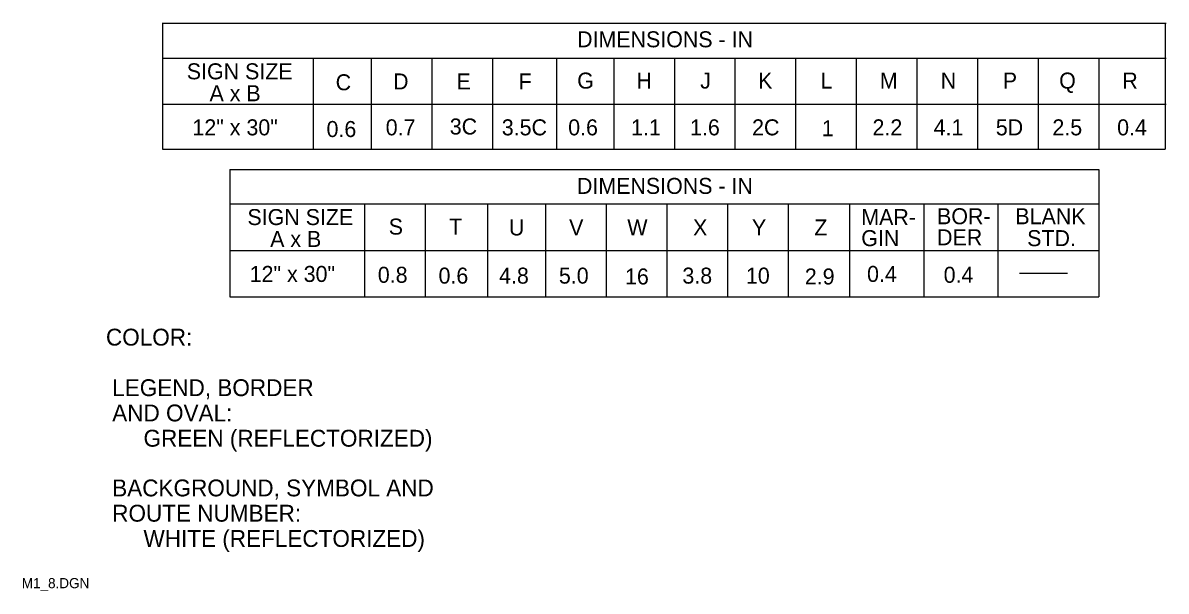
# Model space of a CAD drawing. Extents: x 0.013 to 0.192, y 0.004 to 0.259.
# Drawn here: x 0.0127 to 0.1824, y 0.0039 to 0.0882 of the extents above; entities that cross this region are included whole.
import ezdxf

# ---------------------------------------------------------------- set-up
doc = ezdxf.new("R2010")
doc.units = 0
doc.layers.add('1', color=7, linetype='Continuous')
doc.layers.add('3', color=7, linetype='Continuous')

msp = doc.modelspace()

# ---------------------------------------------------------------- linework, layer by layer
at = {"layer": '1'}
msp.add_line((0.160625, 0.051125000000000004), (0.16775, 0.051125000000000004), dxfattribs=at)
at = {"layer": '3'}
for p, q in [((0.033375, 0.08825), (0.033375, 0.0695)), ((0.03350466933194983, 0.08821109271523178), (0.18237966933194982, 0.08821109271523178)), ((0.18225, 0.08825), (0.18225, 0.0695)), ((0.18237966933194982, 0.08294507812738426), (0.03345683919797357, 0.08294507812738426)), ((0.05575, 0.083), (0.05575, 0.0695)), ((0.064375, 0.083), (0.064375, 0.0695)), ((0.073375, 0.083), (0.073375, 0.0695)), ((0.082375, 0.083), (0.082375, 0.0695)), ((0.091875, 0.083), (0.091875, 0.0695)), ((0.100375, 0.083), (0.100375, 0.0695)), ((0.109375, 0.083), (0.109375, 0.0695)), ((0.11837500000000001, 0.083), (0.11837500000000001, 0.0695)), ((0.12737500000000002, 0.083), (0.12737500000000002, 0.0695)), ((0.136375, 0.083), (0.136375, 0.0695)), ((0.145375, 0.083), (0.145375, 0.0695)), ((0.154375, 0.083), (0.154375, 0.0695)), ((0.163375, 0.083), (0.163375, 0.0695)), ((0.172375, 0.083), (0.172375, 0.0695)), ((0.03350466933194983, 0.07621109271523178), (0.18237966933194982, 0.07621109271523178)), ((0.033375, 0.0695), (0.18225, 0.0695)), ((0.043375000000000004, 0.0665), (0.172375, 0.0665)), ((0.043375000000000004, 0.0665), (0.043375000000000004, 0.047625)), ((0.172375, 0.0665), (0.172375, 0.047625)), ((0.172375, 0.061375), (0.043375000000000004, 0.061375)), ((0.063375, 0.061375), (0.063375, 0.047625)), ((0.072375, 0.061375), (0.072375, 0.047625)), ((0.0816495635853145, 0.061329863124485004), (0.0816495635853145, 0.04758609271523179)), ((0.09025, 0.061375), (0.09025, 0.047625)), ((0.09925, 0.061375), (0.09925, 0.047625)), ((0.10825, 0.061375), (0.10825, 0.047625)), ((0.11725000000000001, 0.061375), (0.11725000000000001, 0.047625)), ((0.12625, 0.061375), (0.12625, 0.047625)), ((0.13539128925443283, 0.061329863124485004), (0.13539128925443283, 0.04758609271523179)), ((0.14639128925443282, 0.061329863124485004), (0.14639128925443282, 0.04758609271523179)), ((0.15739128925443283, 0.061329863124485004), (0.15739128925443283, 0.04758609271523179)), ((0.043375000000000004, 0.0545), (0.172375, 0.0545)), ((0.043375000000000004, 0.047625), (0.172375, 0.047625))]:
    msp.add_line(p, q, dxfattribs=at)

# ---------------------------------------------------------------- texts
at = {"layer": '1'}
for s, height, p in [('COLOR:', 0.0024997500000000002, (0.025, 0.040375)), (' LEGEND, BORDER', 0.0024997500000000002, (0.025, 0.032875)), (' AND OVAL:', 0.0024997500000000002, (0.025, 0.029125)), ('      GREEN (REFLECTORIZED)', 0.0024997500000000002, (0.025, 0.025375)), (' BACKGROUND, SYMBOL AND', 0.0024997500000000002, (0.025, 0.018000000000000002)), (' ROUTE NUMBER:', 0.0024997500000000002, (0.025, 0.01425)), ('      WHITE (REFLECTORIZED)', 0.0024997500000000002, (0.025, 0.0105)), ('M1_8.DGN', 0.0015, (0.0125, 0.004375))]:
    msp.add_text(s, height=height, dxfattribs=at).set_placement(p)
at = {"layer": '3'}
for s, height, p in [('DIMENSIONS - IN', 0.0023745, (0.09494003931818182, 0.084625)), ('SIGN SIZE', 0.0023752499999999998, (0.037, 0.079875)), ('C', 0.0023745, (0.059100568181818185, 0.07825)), ('D', 0.0023745, (0.067625, 0.078375)), ('E', 0.0023745, (0.07703457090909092, 0.078375)), ('F', 0.0023745, (0.08625000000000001, 0.078375)), ('G', 0.0023745, (0.09495578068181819, 0.0785)), ('H', 0.0023752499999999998, (0.10375000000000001, 0.0785)), ('J', 0.0023752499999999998, (0.1132144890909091, 0.0785)), ('K', 0.0023752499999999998, (0.12180709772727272, 0.0785)), ('L', 0.0023752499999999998, (0.13108684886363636, 0.0785)), ('M', 0.0023752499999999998, (0.139875, 0.0785)), ('N', 0.0023752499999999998, (0.1489141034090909, 0.0785)), ('P', 0.0023752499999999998, (0.158129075, 0.0785)), ('Q', 0.0023752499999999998, (0.1665, 0.0785)), ('R', 0.0023752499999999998, (0.175875, 0.0785)), ('A x B', 0.0023752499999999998, (0.040375, 0.076625)), ('12" x 30"', 0.0023752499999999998, (0.037836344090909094, 0.071562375)), ('0.6', 0.0023752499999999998, (0.057743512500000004, 0.07131237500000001)), ('0.7', 0.0023752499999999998, (0.06652914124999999, 0.071562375)), ('3C', 0.0023752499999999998, (0.07603957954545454, 0.071687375)), ('3.5C', 0.0023752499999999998, (0.08376102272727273, 0.071562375)), ('0.6', 0.0023752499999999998, (0.0936185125, 0.071562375)), ('1.1', 0.0023752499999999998, (0.10295632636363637, 0.071562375)), ('1.6', 0.0023752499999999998, (0.11170944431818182, 0.071562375)), ('2C', 0.0023752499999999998, (0.12091457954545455, 0.071562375)), ('1', 0.0023752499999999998, (0.13126895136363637, 0.07143737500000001)), ('2.2', 0.0023752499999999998, (0.13879497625, 0.071562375)), ('4.1', 0.0023752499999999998, (0.14786539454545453, 0.071562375)), ('5D', 0.0023752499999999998, (0.1570965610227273, 0.071562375)), ('2.5', 0.0023752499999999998, (0.1654963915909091, 0.071562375)), ('0.4', 0.0023752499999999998, (0.17510699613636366, 0.071562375)), ('DIMENSIONS - IN', 0.0023745, (0.09492138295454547, 0.06287500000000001)), ('SIGN SIZE', 0.0023752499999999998, (0.046, 0.05825)), ('MAR-', 0.0023752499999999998, (0.137125, 0.05825)), ('BOR-', 0.0023752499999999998, (0.148375, 0.058375)), ('BLANK', 0.0023752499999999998, (0.16, 0.058375)), ('S', 0.0023752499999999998, (0.06697507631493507, 0.05683508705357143)), ('T', 0.0023752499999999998, (0.07595636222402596, 0.05683508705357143)), ('U', 0.0023752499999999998, (0.08481744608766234, 0.05671008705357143)), ('V', 0.0023752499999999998, (0.0937554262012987, 0.05671008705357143)), ('W', 0.0023752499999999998, (0.10239314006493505, 0.05671008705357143)), ('X', 0.0023752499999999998, (0.11214938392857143, 0.05671008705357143)), ('Y', 0.0023752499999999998, (0.12089938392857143, 0.05671008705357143)), ('Z', 0.0023752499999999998, (0.13014921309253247, 0.05671008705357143)), ('A x B', 0.0023752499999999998, (0.049375, 0.055)), ('GIN', 0.0023752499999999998, (0.137125, 0.055125)), ('DER', 0.0023752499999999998, (0.148375, 0.05525)), ('STD.', 0.0023752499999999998, (0.16175, 0.055125)), ('12" x 30"', 0.0023752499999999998, (0.046336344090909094, 0.049812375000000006)), ('0.8', 0.0023752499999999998, (0.0653555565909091, 0.049687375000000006)), ('0.6', 0.0023752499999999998, (0.0743685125, 0.049562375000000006)), ('4.8', 0.0023752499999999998, (0.0833555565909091, 0.049562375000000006)), ('5.0', 0.0023752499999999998, (0.0922384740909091, 0.049562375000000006)), ('16', 0.0023752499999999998, (0.1020522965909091, 0.049437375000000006)), ('3.8', 0.0023752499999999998, (0.11057017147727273, 0.049562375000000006)), ('10', 0.0023752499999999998, (0.12000251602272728, 0.049562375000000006)), ('2.9', 0.0023752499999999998, (0.12874711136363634, 0.049437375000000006)), ('0.4', 0.0023752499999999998, (0.13798199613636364, 0.049812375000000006)), ('0.4', 0.0023752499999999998, (0.14935699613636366, 0.049687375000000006))]:
    msp.add_text(s, height=height, dxfattribs=at).set_placement(p)

doc.saveas('drawing.dxf')
